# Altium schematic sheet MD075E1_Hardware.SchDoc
size A
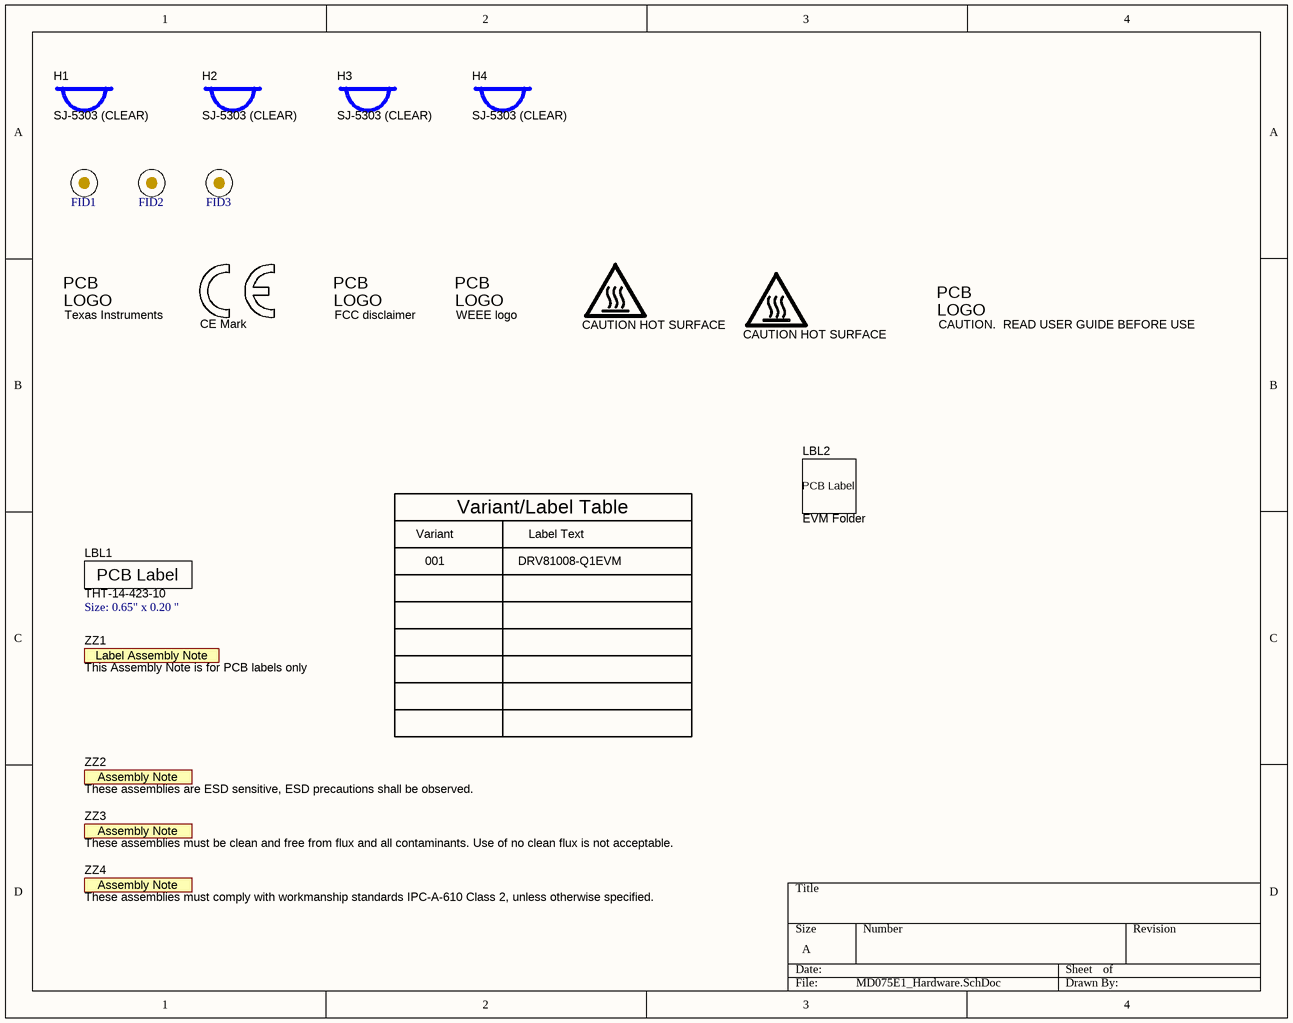
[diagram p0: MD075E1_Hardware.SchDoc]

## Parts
FID1  Fiducial  [Fiducial10-20]  (value not drawn)
FID2  Fiducial  [Fiducial10-20]  (value not drawn)
FID3  Fiducial  [Fiducial10-20]  (value not drawn)
H1  SJ-5303 (CLEAR)  [Bumpon_SJ5003Transparent]
H2  SJ-5303 (CLEAR)  [Bumpon_SJ5003Transparent]
H3  SJ-5303 (CLEAR)  [Bumpon_SJ5003Transparent]
H4  SJ-5303 (CLEAR)  [Bumpon_SJ5003Transparent]
LBL1  THT-14-423-10  Note: Size: 0.65" x 0.20 "  [Label_650x200]
LBL2  EVM Folder  [Label_375x375]
Logo1  CE Mark  [CE_Mark_5mm]  (no BOM)
Logo2  Texas Instruments  [TI_Stacked_Overlay_Small]  (no BOM)
Logo3  FCC disclaimer  [FCC_disclaimer]  (no BOM)
Logo4  WEEE logo  [WEEE_Minimum]  (no BOM)
Logo5  CAUTION.  READ USER GUIDE BEFORE USE  [IEC_Caution_Small]  (no BOM)
LOGO6  CAUTION HOT SURFACE  [IEC_HotSurface_Small]  (no BOM)
LOGO7  CAUTION HOT SURFACE  [IEC_HotSurface_Small]  (no BOM)
ZZ1  This Assembly Note is for PCB labels only  [AssemblyNoteLabel]  (no BOM)
ZZ2  These assemblies are ESD sensitive, ESD precautions shall be observed.  [AssemblyNote]  (no BOM)
ZZ3  These assemblies must be clean and free from flux and all contaminants. Use of no clean flux is not acceptable.  [AssemblyNote]  (no BOM)
ZZ4  These assemblies must comply with workmanship standards IPC-A-610 Class 2, unless otherwise specified.  [AssemblyNote]  (no BOM)

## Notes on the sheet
- Variant/Label Table
- Variant
- 001
- Label Text
- DRV81008-Q1EVM

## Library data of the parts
FID1-FID3 = CMP-0077181-1: Fiducial mark.  There is nothing to buy or mount.
H1-H4 = CMP-0003620-1: Bumpon, Hemisphere, 0.44 X 0.20, Clear; Manufacturer: 3M
LBL1 = CMP-0003625-1: Thermal Transfer Printable Labels, 0.650" W x 0.200" H - 10,000 per roll; Manufacturer: Brady
LBL2 = CMP-00007-1: Harsh Environment Multi-Purpose Polyester Labels for 3" Core Printers - 0.375" x 0.375", White; Manufacturer: Brady; PartNumber: THT-14-423-10; Body Material: PET,Polyester; Note: Size: 0.375" x 0.375"
Logo1 = CMP-0074844-1: SymbolCreator: a0412235
Logo2 = CMP-0074838-1: Texas Instrument Corporate Signature; SymbolCreator: a0412235; Lib Reference: TI_Logo
Logo3 = CMP-0074847-1: FCC_disclaimer
Logo4 = CMP-0074769-3: Manufacturer: Texas Instruments; CompType: IC; AEC Category: Q200
Logo5 = CMP-0074836-1: IEC 61010-1 Caution Warning; SymbolCreator: a0412235; Lib Reference: IEC_Caution
LOGO6 LOGO7 = CMP-0074837-2: IEC 61010-1 Hot Surface Warning; Manufacturer: Texas Instruments; SymbolCreator: a0412235; CompType: IC; AEC Category: Q200
ZZ1 = CMP-0003616-3
ZZ2 = CMP-0077236-1
ZZ3 = CMP-0077237-1
ZZ4 = CMP-0077238-1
